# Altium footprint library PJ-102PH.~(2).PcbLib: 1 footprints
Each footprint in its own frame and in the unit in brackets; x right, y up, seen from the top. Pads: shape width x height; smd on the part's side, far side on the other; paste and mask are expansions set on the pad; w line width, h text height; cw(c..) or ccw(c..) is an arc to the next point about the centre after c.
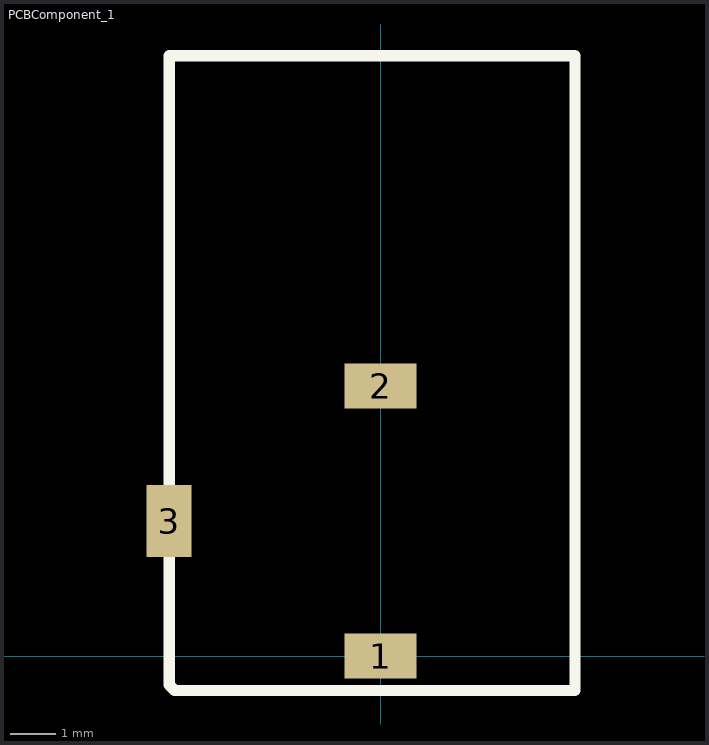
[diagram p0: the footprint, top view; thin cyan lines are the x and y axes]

## PCBComponent_1 [mm]
pads (3):
  rect 1.6x1 all layers, no hole: 1(0,0) 2(0,6)
  rect 1x1.6 all layers, no hole: 3(-4.7,3)
Top Overlay:
  lines w0.254: -4.699,-0.635 -4.699,13.335 4.318,13.335 4.318,-0.762 -4.572,-0.762 -4.699,-0.635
